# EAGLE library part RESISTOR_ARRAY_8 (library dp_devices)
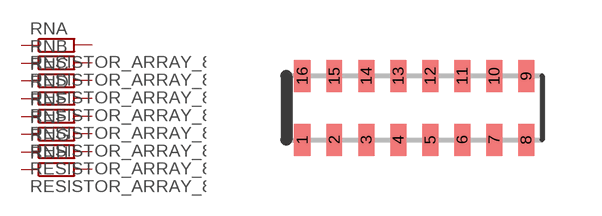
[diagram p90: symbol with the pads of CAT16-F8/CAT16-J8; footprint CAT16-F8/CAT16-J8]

Designator prefix RN; gates A=RESISTOR B=RESISTOR C=RESISTOR D=RESISTOR E=RESISTOR F=RESISTOR G=RESISTOR H=RESISTOR

## RESISTOR_ARRAY_8  [CAT16-F8/CAT16-J8]
1  A:1  pas
2  B:1  pas
3  C:1  pas
4  D:1  pas
5  E:1  pas
6  F:1  pas
7  G:1  pas
8  H:1  pas
9  H:2  pas
10  G:2  pas
11  F:2  pas
12  E:2  pas
13  D:2  pas
14  C:2  pas
15  B:2  pas
16  A:2  pas

## Footprint CAT16-F8/CAT16-J8 (pad centres in mm)
smd 0.4 x 0.8: 1 -2.4,-0.8; 2 -1.6,-0.8; 3 -0.8,-0.8; 4 0,-0.8; 5 0.8,-0.8; 6 1.6,-0.8; 7 2.4,-0.8; 8 3.2,-0.8; 9 3.2,0.8; 10 2.4,0.8; 11 1.6,0.8; 12 0.8,0.8; 13 0,0.8; 14 -0.8,0.8; 15 -1.6,0.8; 16 -2.4,0.8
